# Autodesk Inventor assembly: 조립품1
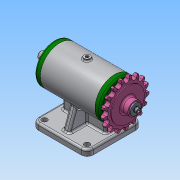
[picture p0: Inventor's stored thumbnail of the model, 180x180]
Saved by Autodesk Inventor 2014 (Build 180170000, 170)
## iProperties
Created: 2019-06
Part Number: 조립품1
Document SubType Name: Assembly
Designer: NET
Author: NET
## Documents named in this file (11)
- C:\Users\NET\Desktop\490604V1037\답안조립품.iam
- C:\Users\NET\Desktop\490604V1037\본체.ipt
- C:\Users\NET\Desktop\490604V1037\축.ipt
- C:\Users\NET\Desktop\490604V1037\베어링 6203.ipt
- C:\Users\NET\Desktop\490604V1037\커버.ipt
- C:\Users\NET\Desktop\490604V1037\오일 실 17 30 5.ipt
- C:\Users\NET\Desktop\490604V1037\키 4x4x12.ipt
- C:\Users\NET\Desktop\490604V1037\평와셔.ipt
- C:\Users\NET\Desktop\490604V1037\스프로킷.ipt
- C:\Users\NET\Desktop\490604V1037\스프링와셔.ipt
- C:\Users\NET\Desktop\490604V1037\볼트 M4.ipt
